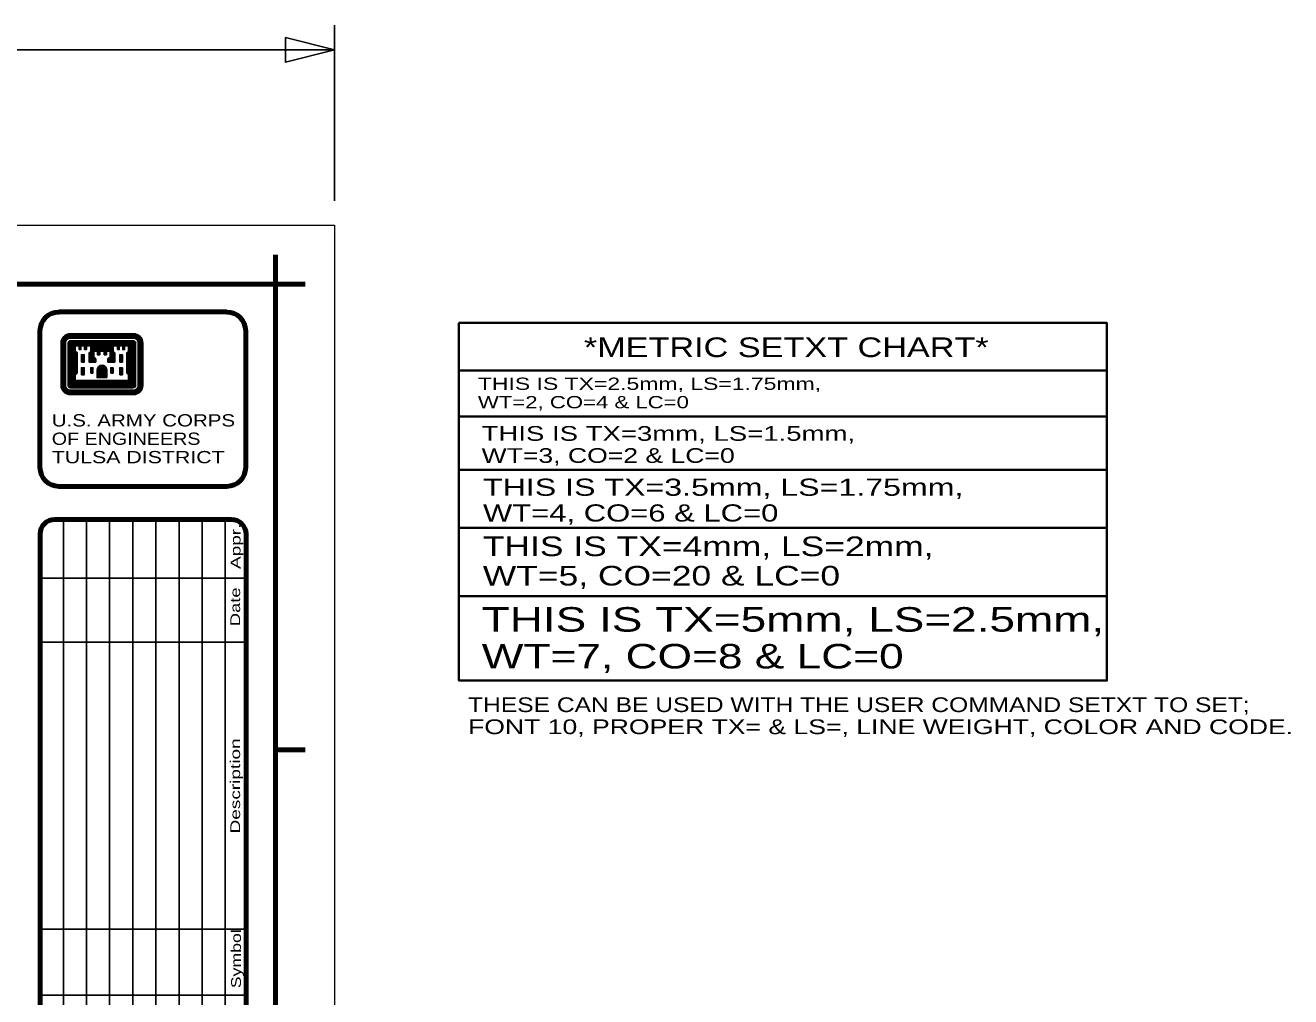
# Model space of a CAD drawing. Extents: x 55 to 190, y 198 to 264.
# Drawn here: x 140.29 to 166.09, y 242.12 to 261.93 of the extents above; entities that cross this region are included whole.
import ezdxf
from ezdxf.enums import TextEntityAlignment as Align

# ---------------------------------------------------------------- set-up
doc = ezdxf.new("R2010")
doc.units = 0
doc.header["$LTSCALE"] = 0.1
for name, color, linetype, lineweight in [('1', 7, 'Continuous', 25), ('3', 7, 'Continuous', 25), ('5', 7, 'Continuous', 35)]:
    doc.layers.add(name, color=color, linetype=linetype, lineweight=lineweight)

msp = doc.modelspace()

# ---------------------------------------------------------------- linework, layer by layer
at = {"layer": '1', "lineweight": 80}
for p, q in [((145.3927, 257.2525), (145.3927, 256.6525)), ((145.9927, 256.6525), (145.3927, 256.6525)), ((140.974, 256.085), (144.399, 256.085)), ((140.5865, 252.9137), (140.5865, 255.6962)), ((144.784, 252.9137), (144.784, 255.6962)), ((140.974, 252.5275), (144.399, 252.5275)), ((144.4902, 251.8525), (140.8902, 251.8525)), ((140.5902, 251.5525), (140.5902, 232.7525)), ((144.7902, 232.7525), (144.7902, 251.5525)), ((145.9927, 247.1525), (145.3927, 247.1525))]:
    msp.add_line(p, q, dxfattribs=at)
at = {"layer": '1'}
for p, q in [((141.0177, 254.5862), (141.0177, 255.4525)), ((141.0352, 254.5075), (141.0352, 255.5287)), ((141.0615, 254.4675), (141.0615, 255.57)), ((141.0852, 254.4437), (141.0852, 255.5937)), ((141.1102, 255.455), (141.1102, 255.61)), ((141.1102, 254.5825), (141.1102, 255.455)), ((141.1315, 255.5175), (141.1315, 255.6225)), ((141.1565, 255.5387), (141.1565, 255.6325)), ((141.1627, 254.5862), (141.1627, 255.4525)), ((141.1802, 255.5437), (141.1802, 255.6375)), ((141.1802, 254.5525), (141.1802, 255.4862)), ((141.204, 255.5525), (141.204, 255.6375)), ((141.204, 255.5525), (142.4977, 255.5525)), ((141.204, 254.54), (141.204, 255.4962)), ((141.2127, 255.64), (142.4915, 255.64)), ((141.2127, 255.4962), (142.4915, 255.4962)), ((141.2302, 255.5525), (141.2302, 255.6375)), ((141.2302, 254.54), (141.2302, 255.4962)), ((141.2527, 255.5525), (141.2527, 255.6375)), ((141.2527, 254.54), (141.2527, 255.4962)), ((141.2777, 255.5525), (141.2777, 255.6375)), ((141.2777, 254.54), (141.2777, 255.4962)), ((141.3027, 255.5525), (141.3027, 255.6375)), ((141.3027, 254.54), (141.3027, 255.4962)), ((141.3252, 255.5525), (141.3252, 255.6375)), ((141.3252, 255.3912), (141.3252, 255.4962)), ((141.3527, 255.5525), (141.3527, 255.6375)), ((141.3527, 255.3912), (141.3527, 255.4962)), ((141.3727, 255.5525), (141.3727, 255.6375)), ((141.3727, 255.3912), (141.3727, 255.4962)), ((141.4015, 255.5525), (141.4015, 255.6375)), ((141.4015, 255.3187), (141.4015, 255.4962)), ((141.4215, 255.5525), (141.4215, 255.6375)), ((141.4215, 255.3187), (141.4215, 255.4962)), ((141.4477, 255.5525), (141.4477, 255.6375)), ((141.4477, 255.3912), (141.4477, 255.4962)), ((141.4702, 255.5525), (141.4702, 255.6375)), ((141.4702, 255.3912), (141.4702, 255.4962)), ((141.4952, 255.5525), (141.4952, 255.6375)), ((141.4952, 255.3912), (141.4952, 255.4962)), ((141.519, 255.5525), (141.519, 255.6375)), ((141.519, 255.3212), (141.519, 255.4962)), ((141.5427, 255.5525), (141.5427, 255.6375)), ((141.5427, 255.3912), (141.5427, 255.4962)), ((141.5652, 255.5525), (141.5652, 255.6375)), ((141.5652, 255.3912), (141.5652, 255.4962)), ((141.5927, 255.5525), (141.5927, 255.6375)), ((141.5927, 255.3912), (141.5927, 255.4962)), ((141.6152, 255.5525), (141.6152, 255.6375)), ((141.6152, 255.3912), (141.6152, 255.4962)), ((141.6402, 255.5525), (141.6402, 255.6375)), ((141.6402, 255.0612), (141.6402, 255.4962)), ((141.664, 255.5525), (141.664, 255.6375)), ((141.664, 255.0612), (141.664, 255.4962)), ((141.689, 255.5525), (141.689, 255.6375)), ((141.689, 255.2862), (141.689, 255.4962)), ((141.7127, 255.5525), (141.7127, 255.6375)), ((141.7127, 255.2862), (141.7127, 255.4962)), ((141.7377, 255.5525), (141.7377, 255.6375)), ((141.7377, 255.2862), (141.7377, 255.4962)), ((141.7615, 255.5525), (141.7615, 255.6375)), ((141.7615, 255.2862), (141.7615, 255.4962)), ((141.7865, 255.5525), (141.7865, 255.6375)), ((141.7865, 255.2125), (141.7865, 255.4962)), ((141.8077, 255.5525), (141.8077, 255.6375)), ((141.8077, 255.2862), (141.8077, 255.4962)), ((141.834, 255.5525), (141.834, 255.6375)), ((141.834, 255.2862), (141.834, 255.4962)), ((141.8552, 255.5525), (141.8552, 255.6375)), ((141.8552, 255.2862), (141.8552, 255.4962)), ((141.8815, 255.5525), (141.8815, 255.6375)), ((141.8815, 255.2862), (141.8815, 255.4962)), ((141.9052, 255.5525), (141.9052, 255.6375)), ((141.9052, 255.2125), (141.9052, 255.4962)), ((141.9302, 255.5525), (141.9302, 255.6375)), ((141.9302, 255.2125), (141.9302, 255.4962)), ((141.9552, 255.5525), (141.9552, 255.6375)), ((141.9552, 255.2862), (141.9552, 255.4962)), ((141.979, 255.5525), (141.979, 255.6375)), ((141.979, 255.2862), (141.979, 255.4962)), ((141.979, 255.2862), (141.979, 255.4962)), ((142.0015, 255.5525), (142.0015, 255.6375)), ((142.0015, 255.2862), (142.0015, 255.4962)), ((142.0265, 255.5525), (142.0265, 255.6375)), ((142.0265, 255.0612), (142.0265, 255.4962)), ((142.0502, 255.5525), (142.0502, 255.6375)), ((142.0502, 255.0612), (142.0502, 255.4962)), ((142.074, 255.5525), (142.074, 255.6375)), ((142.074, 255.0612), (142.074, 255.4962)), ((142.0977, 255.5525), (142.0977, 255.6375)), ((142.0977, 255.3912), (142.0977, 255.4962)), ((142.124, 255.5525), (142.124, 255.6375)), ((142.124, 255.3912), (142.124, 255.4962)), ((142.1465, 255.5525), (142.1465, 255.6375)), ((142.1465, 255.3912), (142.1465, 255.4962)), ((142.1727, 255.5525), (142.1727, 255.6375)), ((142.1727, 255.3187), (142.1727, 255.4962)), ((142.1965, 255.5525), (142.1965, 255.6375)), ((142.1965, 255.3187), (142.1965, 255.4962)), ((142.2202, 255.5525), (142.2202, 255.6375)), ((142.2202, 255.3912), (142.2202, 255.4962)), ((142.2427, 255.5525), (142.2427, 255.6375)), ((142.244, 255.3912), (142.244, 255.4962)), ((142.269, 255.5525), (142.269, 255.6375)), ((142.269, 255.3912), (142.269, 255.4962)), ((142.2915, 255.5525), (142.2915, 255.6375)), ((142.2915, 255.3187), (142.2915, 255.4962)), ((142.3165, 255.5525), (142.3165, 255.6375)), ((142.3165, 255.3912), (142.3165, 255.4962)), ((142.3402, 255.5525), (142.3402, 255.6375)), ((142.3402, 255.3912), (142.3402, 255.4962)), ((142.3652, 255.5525), (142.3652, 255.6375)), ((142.3652, 255.3912), (142.3652, 255.4962)), ((142.3902, 255.5525), (142.3902, 255.6375)), ((142.3902, 255.3912), (142.3902, 255.4962)), ((142.4127, 255.5525), (142.4127, 255.6375)), ((142.4127, 254.54), (142.4127, 255.4962)), ((142.4365, 255.5525), (142.4365, 255.6375)), ((142.4365, 254.54), (142.4365, 255.4962)), ((142.4602, 255.5525), (142.4602, 255.6375)), ((142.4602, 254.54), (142.4602, 255.4962)), ((142.484, 255.5525), (142.484, 255.6375)), ((142.484, 254.54), (142.484, 255.4962)), ((142.509, 255.5525), (142.509, 255.6375)), ((142.509, 254.5425), (142.509, 255.4937)), ((142.5327, 255.5437), (142.5327, 255.6375)), ((142.5327, 254.565), (142.5327, 255.4725)), ((142.5365, 254.5862), (142.5365, 255.4525)), ((142.5602, 255.5287), (142.5602, 255.6275)), ((142.5815, 255.5025), (142.5815, 255.62)), ((142.594, 254.5825), (142.594, 255.455)), ((142.6065, 254.4375), (142.6065, 255.6037)), ((142.6327, 254.4575), (142.6327, 255.5775)), ((142.6552, 254.4887), (142.6552, 255.5525)), ((142.679, 254.5512), (142.679, 255.4887)), ((142.6865, 254.5862), (142.6865, 255.4525)), ((141.3277, 254.82), (141.3277, 255.27)), ((141.4477, 255.0612), (141.4477, 255.2125)), ((141.4702, 255.0612), (141.4702, 255.2125)), ((141.5927, 255.0612), (141.5927, 255.255)), ((141.6177, 255.0612), (141.6177, 255.2812)), ((142.1002, 255.0612), (142.1002, 255.2637)), ((142.2052, 255.3912), (142.2765, 255.3912)), ((142.2202, 255.0612), (142.2202, 255.2125)), ((142.2427, 255.0612), (142.2427, 255.2125)), ((142.3652, 254.835), (142.3652, 255.255)), ((142.3902, 254.8112), (142.3902, 255.2812)), ((141.4477, 254.805), (141.4477, 254.9462)), ((141.4702, 254.805), (141.4702, 254.9462)), ((141.6402, 254.8387), (141.6402, 254.9462)), ((141.664, 254.8387), (141.664, 254.9462)), ((141.689, 255.0612), (141.689, 255.16)), ((141.7127, 255.0612), (141.7127, 255.135)), ((141.7615, 254.745), (141.7615, 254.9312)), ((141.7865, 254.745), (141.7865, 254.9675)), ((141.8077, 254.745), (141.8077, 254.9862)), ((141.834, 254.745), (141.834, 254.9987)), ((141.8552, 254.745), (141.8552, 255.0012)), ((141.8815, 254.745), (141.8815, 254.9925)), ((141.9052, 254.745), (141.9052, 254.9787)), ((141.9302, 254.745), (141.9302, 254.9575)), ((141.979, 255.0612), (141.979, 255.1325)), ((142.004, 255.0612), (142.004, 255.15)), ((142.0502, 254.8387), (142.0502, 254.9462)), ((142.074, 254.8387), (142.074, 254.9462)), ((142.2202, 254.805), (142.2202, 254.9462)), ((142.2427, 254.805), (142.2427, 254.9462)), ((141.3252, 254.54), (141.3252, 254.6837)), ((141.3527, 254.54), (141.3527, 254.6837)), ((141.3727, 254.54), (141.3727, 254.6837)), ((141.4015, 254.54), (141.4015, 254.6837)), ((141.4215, 254.54), (141.4215, 254.6837)), ((141.4477, 254.54), (141.4477, 254.6837)), ((141.4702, 254.54), (141.4702, 254.6837)), ((141.4952, 254.54), (141.4952, 254.6837)), ((141.519, 254.54), (141.519, 254.6837)), ((141.5427, 254.54), (141.5427, 254.6837)), ((141.5652, 254.54), (141.5652, 254.6837)), ((141.5927, 254.54), (141.5927, 254.6837)), ((141.6152, 254.54), (141.6152, 254.6837)), ((141.6402, 254.54), (141.6402, 254.6837)), ((141.664, 254.54), (141.664, 254.6837)), ((141.689, 254.54), (141.689, 254.6837)), ((141.7127, 254.54), (141.7127, 254.6837)), ((141.7377, 254.54), (141.7377, 254.6837)), ((141.7515, 254.745), (141.9502, 254.745)), ((141.7615, 254.54), (141.7615, 254.6837)), ((141.7865, 254.54), (141.7865, 254.6837)), ((141.8077, 254.54), (141.8077, 254.6837)), ((141.834, 254.54), (141.834, 254.6837)), ((141.8552, 254.54), (141.8552, 254.6837)), ((141.8815, 254.54), (141.8815, 254.6837)), ((141.9052, 254.54), (141.9052, 254.6837)), ((141.9302, 254.54), (141.9302, 254.6837)), ((141.9552, 254.745), (141.9552, 254.8937)), ((141.9552, 254.54), (141.9552, 254.6837)), ((141.979, 254.54), (141.979, 254.6837)), ((142.0015, 254.54), (142.0015, 254.6837)), ((142.0265, 254.54), (142.0265, 254.6837)), ((142.0502, 254.54), (142.0502, 254.6837)), ((142.074, 254.54), (142.074, 254.6837)), ((142.0977, 254.54), (142.0977, 254.6837)), ((142.124, 254.54), (142.124, 254.6837)), ((142.1465, 254.54), (142.1465, 254.6837)), ((142.1727, 254.54), (142.1727, 254.6837)), ((142.1965, 254.54), (142.1965, 254.6837)), ((142.2202, 254.54), (142.2202, 254.6837)), ((142.2427, 254.54), (142.2427, 254.6837)), ((142.269, 254.54), (142.269, 254.6837)), ((142.2915, 254.54), (142.2915, 254.6837)), ((142.3165, 254.54), (142.3165, 254.6837)), ((142.3402, 254.54), (142.3402, 254.6837)), ((142.3652, 254.54), (142.3652, 254.6837)), ((142.3902, 254.54), (142.3902, 254.6837)), ((141.1102, 254.4287), (141.1102, 254.5825)), ((141.1315, 254.415), (141.1315, 254.5212)), ((141.1565, 254.4037), (141.1565, 254.5)), ((141.1802, 254.4), (141.1802, 254.4912)), ((141.204, 254.54), (142.484, 254.54)), ((141.204, 254.4887), (142.4977, 254.4887)), ((141.204, 254.4), (141.204, 254.4887)), ((141.2127, 254.3987), (142.4915, 254.3987)), ((141.2302, 254.4), (141.2302, 254.4887)), ((141.2527, 254.4), (141.2527, 254.4887)), ((141.2777, 254.4), (141.2777, 254.4887)), ((141.3027, 254.4), (141.3027, 254.4887)), ((141.3252, 254.4), (141.3252, 254.4887)), ((141.3527, 254.4), (141.3527, 254.4887)), ((141.3727, 254.4), (141.3727, 254.4887)), ((141.4015, 254.4), (141.4015, 254.4887)), ((141.4215, 254.4), (141.4215, 254.4887)), ((141.4477, 254.4), (141.4477, 254.4887)), ((141.4702, 254.4), (141.4702, 254.4887)), ((141.4952, 254.4), (141.4952, 254.4887)), ((141.519, 254.4), (141.519, 254.4887)), ((141.5427, 254.4), (141.5427, 254.4887)), ((141.5652, 254.4), (141.5652, 254.4887)), ((141.5927, 254.4), (141.5927, 254.4887)), ((141.6152, 254.4), (141.6152, 254.4887)), ((141.6402, 254.4), (141.6402, 254.4887)), ((141.664, 254.4), (141.664, 254.4887)), ((141.689, 254.4), (141.689, 254.4887)), ((141.7127, 254.4), (141.7127, 254.4887)), ((141.7377, 254.4), (141.7377, 254.4887)), ((141.7615, 254.4), (141.7615, 254.4887)), ((141.7865, 254.4), (141.7865, 254.4887)), ((141.8077, 254.4), (141.8077, 254.4887)), ((141.834, 254.4), (141.834, 254.4887)), ((141.8552, 254.4), (141.8552, 254.4887)), ((141.8815, 254.4), (141.8815, 254.4887)), ((141.9052, 254.4), (141.9052, 254.4887)), ((141.9302, 254.4), (141.9302, 254.4887)), ((141.9552, 254.4), (141.9552, 254.4887)), ((141.979, 254.4), (141.979, 254.4887)), ((142.0015, 254.4), (142.0015, 254.4887)), ((142.0265, 254.4), (142.0265, 254.4887)), ((142.0502, 254.4), (142.0502, 254.4887)), ((142.074, 254.4), (142.074, 254.4887)), ((142.0977, 254.4), (142.0977, 254.4887)), ((142.124, 254.4), (142.124, 254.4887)), ((142.1465, 254.4), (142.1465, 254.4887)), ((142.1727, 254.4), (142.1727, 254.4887)), ((142.1965, 254.4), (142.1965, 254.4887)), ((142.2202, 254.4), (142.2202, 254.4887)), ((142.2427, 254.4), (142.2427, 254.4887)), ((142.269, 254.4), (142.269, 254.4887)), ((142.2915, 254.4), (142.2915, 254.4887)), ((142.3165, 254.4), (142.3165, 254.4887)), ((142.3402, 254.4), (142.3402, 254.4887)), ((142.3652, 254.4), (142.3652, 254.4887)), ((142.3902, 254.4), (142.3902, 254.4887)), ((142.4127, 254.4), (142.4127, 254.4887)), ((142.4365, 254.4), (142.4365, 254.4887)), ((142.4602, 254.4), (142.4602, 254.4887)), ((142.484, 254.4), (142.484, 254.4887)), ((142.509, 254.4), (142.509, 254.4887)), ((142.5327, 254.4012), (142.5327, 254.495)), ((142.5602, 254.4075), (142.5602, 254.5075)), ((142.5815, 254.4187), (142.5815, 254.5362)), ((141.0665, 251.8525), (141.0665, 232.4525)), ((141.5377, 251.8525), (141.5377, 232.4525)), ((142.009, 251.8525), (142.009, 232.4525)), ((142.4815, 251.8525), (142.4815, 232.4525)), ((142.9527, 251.8525), (142.9527, 232.4525)), ((143.4252, 251.8525), (143.4252, 232.4525)), ((143.8965, 251.8525), (143.8965, 232.4525)), ((144.3677, 251.8525), (144.3677, 232.4525)), ((140.5965, 250.6525), (144.7902, 250.6525)), ((140.5965, 249.3525), (144.7902, 249.3525)), ((140.5902, 243.4987), (144.7902, 243.4987)), ((144.7902, 242.15), (140.5902, 242.15))]:
    msp.add_line(p, q, dxfattribs=at)
at = {"layer": '1', "lineweight": 13}
msp.add_lwpolyline([(62.4915, 257.8525), (146.5927, 257.8525), (146.5927, 198.4512), (62.4915, 198.4512)], close=True, dxfattribs=at)
at = {"layer": '1', "lineweight": 80}
msp.add_lwpolyline([(65.1915, 256.6525), (145.3927, 256.6525), (145.3927, 199.6512), (65.1915, 199.6512)], close=True, dxfattribs=at)
at = {"layer": '1'}
for points in [[(141.3077, 254.6837), (141.3077, 254.7987), (141.344, 254.8387), (141.344, 255.2512), (141.3077, 255.2862), (141.3077, 255.3912), (141.3902, 255.3912), (141.3902, 255.3187), (141.424, 255.3187), (141.424, 255.3912), (141.4977, 255.3912), (141.4977, 255.3187), (141.534, 255.3187), (141.534, 255.3912), (141.624, 255.3912), (141.624, 255.2862), (141.5902, 255.2512), (141.5902, 255.0612), (141.7252, 255.0612)], [(141.3077, 254.6837), (141.3077, 254.7987), (141.344, 254.8387), (141.344, 255.2512), (141.3077, 255.2862), (141.3077, 255.3912), (141.3902, 255.3912), (141.3902, 255.3187), (141.424, 255.3187), (141.424, 255.3912), (141.4977, 255.3912), (141.4977, 255.3187), (141.534, 255.3187), (141.534, 255.3912), (141.624, 255.3912), (141.624, 255.2862), (141.5902, 255.2512), (141.5902, 255.0612), (141.7252, 255.0612), (141.7252, 255.1275), (141.689, 255.16), (141.689, 255.2862), (141.7615, 255.2862), (141.7615, 255.2125), (141.8065, 255.2125), (141.8065, 255.2862), (141.899, 255.2862), (141.899, 255.2125), (141.9427, 255.2125), (141.9427, 255.2862), (142.0177, 255.2862), (142.0177, 255.16), (141.969, 255.1275), (141.969, 255.0612), (142.1127, 255.0612), (142.1127, 255.2512), (142.079, 255.2862), (142.079, 255.3912), (142.169, 255.3912), (142.169, 255.3187)], [(142.2765, 255.3912), (142.2765, 255.3187), (142.314, 255.3187), (142.314, 255.3912), (142.3965, 255.3912), (142.3965, 255.2862), (142.359, 255.2512), (142.359, 254.8387), (142.3965, 254.805), (142.3965, 254.6837), (141.3077, 254.6837)], [(142.169, 255.3187), (142.2052, 255.3187), (142.2052, 255.3912)], [(141.9552, 254.745), (141.7515, 254.745), (141.7515, 254.8937)]]:
    msp.add_lwpolyline(points, dxfattribs=at)
for points in [[(141.4352, 255.0612), (141.4352, 255.2125), (141.4915, 255.2125), (141.4915, 255.0612)], [(142.214, 255.0612), (142.214, 255.2125), (142.269, 255.2125), (142.269, 255.0612)], [(141.4352, 254.805), (141.4352, 254.9462), (141.4915, 254.9462), (141.4915, 254.805)], [(141.624, 254.8387), (141.624, 254.9462), (141.6677, 254.9462), (141.6677, 254.8387)], [(142.0327, 254.8387), (142.0327, 254.9462), (142.079, 254.9462), (142.079, 254.8387)], [(142.214, 254.805), (142.214, 254.9462), (142.269, 254.9462), (142.269, 254.805)]]:
    msp.add_lwpolyline(points, close=True, dxfattribs=at)
at = {"layer": '1', "lineweight": 80}
for centre, radius, start, end in [((140.9735, 255.6979), 0.3845, 90, 180), ((144.3984, 255.6979), 0.3845, 0, 90), ((140.9735, 252.9117), 0.3845, 180, 270), ((144.3984, 252.9117), 0.3845, 270, 0), ((140.89, 251.5521), 0.3, 90, 180), ((144.4899, 251.5521), 0.3, 0, 90)]:
    msp.add_arc(centre, radius, start, end, dxfattribs=at)
at = {"layer": '1'}
for centre, major_axis, start_param, end_param in [((141.2126, 255.4508), (-0.1932, 0), 4.712389, 6.2831853), ((141.2068, 255.4565), (-0.0966, 0), 4.712389, 6.2831853), ((141.2126, 255.4508), (-0.0483, 0), 4.712389, 6.2831853), ((142.4915, 255.4508), (-0.1932, 0), 3.1415927, 4.712389), ((142.4915, 255.4508), (-0.0483, 0), 3.1415927, 4.712389), ((142.4973, 255.4565), (-0.0966, 0), 3.1415927, 4.712389), ((141.8697, 254.8884), (-0.117, 0), 4.8471589, 6.2333239), ((141.8383, 254.8884), (-0.117, 0), 3.191454, 4.577619), ((141.2126, 254.5873), (-0.1932, 0), 6.2831853, 7.8539816), ((141.2068, 254.5817), (0.0966, 0), 3.1415927, 4.712389), ((141.2126, 254.5873), (0.0483, 0), 3.1415927, 4.712389), ((142.4915, 254.5873), (0.1932, 0), 4.712389, 6.2831853), ((142.4915, 254.5873), (0.0483, 0), 4.712389, 6.2831853), ((142.4973, 254.5817), (0.0966, 0), 4.712389, 6.2831853)]:
    msp.add_ellipse(centre, major_axis=major_axis, ratio=0.9801, start_param=start_param, end_param=end_param, dxfattribs=at)
at = {"layer": '3'}
for p, q in [((146.5927, 258.3525), (146.5927, 261.9312)), ((62.4915, 261.4312), (146.5927, 261.4312))]:
    msp.add_line(p, q, dxfattribs=at)
msp.add_lwpolyline([(145.5927, 261.6812), (146.5927, 261.4312), (145.5927, 261.1812)], close=True, dxfattribs=at)
at = {"layer": '3', "lineweight": 35}
msp.add_lwpolyline([(149.129, 255.86), (162.3427, 255.86), (162.3427, 248.565), (149.129, 248.565)], close=True, dxfattribs=at)
at = {"layer": '5'}
for p, q in [((149.129, 254.89), (162.3427, 254.89)), ((149.129, 253.95), (162.3427, 253.95)), ((149.129, 252.8625), (162.3427, 252.8625)), ((149.129, 251.6837), (162.3427, 251.6837)), ((149.129, 250.2875), (162.3427, 250.2875))]:
    msp.add_line(p, q, dxfattribs=at)

# ---------------------------------------------------------------- texts
at = {"layer": '1'}
for s, width, p in [('U.S. ARMY CORPS', 1.25, (140.829, 253.7487)), ('OF ENGINEERS', 1.2, (140.829, 253.3737)), ('TULSA DISTRICT', 1.3, (140.829, 252.9987))]:
    msp.add_text(s, height=0.25, dxfattribs=dict(at, width=width)).set_placement(p)
for s, width, p in [('Appr.', 1.45, (144.6777, 250.8412)), ('Date', 1.4, (144.669, 249.675)), ('Description', 1.45, (144.669, 245.4475)), ('Symbol', 1.35, (144.6865, 242.2912))]:
    msp.add_text(s, height=0.2, rotation=90, dxfattribs=dict(at, width=width)).set_placement(p)
at = {"layer": '3'}
for s, height, width, p in [('THIS IS TX=2.5mm, LS=1.75mm,', 0.25, 1.4, (149.5177, 254.495)), ('WT=2, CO=4 & LC=0', 0.25, 1.35, (149.5177, 254.12)), ('THIS IS TX=3mm, LS=1.5mm,', 0.3, 1.4, (149.5927, 253.4562)), ('WT=3, CO=2 & LC=0', 0.3, 1.35, (149.5927, 253.0062)), ('THIS IS TX=3.5mm, LS=1.75mm,', 0.35, 1.4, (149.6215, 252.335)), ('WT=4, CO=6 & LC=0', 0.35, 1.35, (149.6215, 251.81)), ('THIS IS TX=4mm, LS=2mm,', 0.4, 1.35, (149.6177, 251.105)), ('WT=5, CO=20 & LC=0', 0.4, 1.35, (149.6177, 250.505)), ('THIS IS TX=5mm, LS=2.5mm,', 0.5, 1.4, (149.5952, 249.5637)), ('WT=7, CO=8 & LC=0', 0.5, 1.35, (149.5952, 248.8137))]:
    msp.add_text(s, height=height, dxfattribs=dict(at, width=width)).set_placement(p)
at = {"layer": '5', "width": 1.3}
msp.add_text('*METRIC SETXT CHART*', height=0.4012, dxfattribs=at).set_placement((155.8052, 255.1637), align=Align.CENTER)
at = {"layer": '5'}
for s, width, p in [('THESE CAN BE USED WITH THE USER COMMAND SETXT TO SET;', 1.25, (149.3165, 247.9237)), ('FONT 10, PROPER TX= & LS=, LINE WEIGHT, COLOR AND CODE.', 1.35, (149.3165, 247.4737))]:
    msp.add_text(s, height=0.3, dxfattribs=dict(at, width=width)).set_placement(p)

doc.saveas('drawing.dxf')
